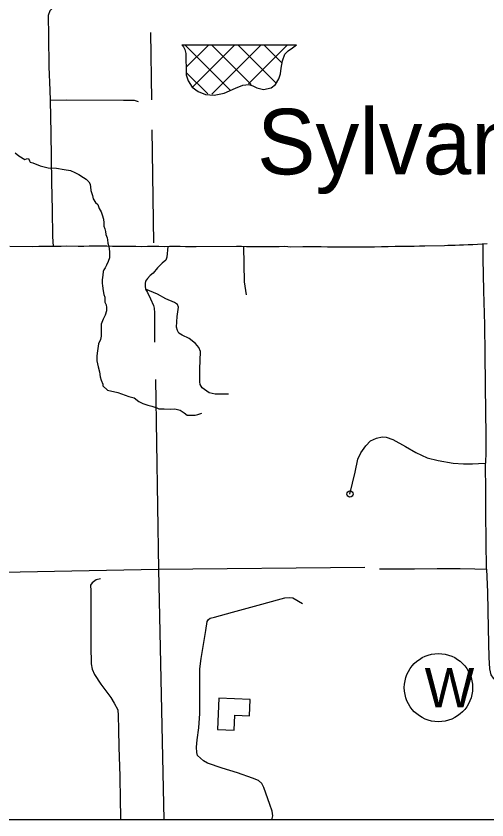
# Model space of a CAD drawing. Extents: x 1367863 to 1368197, y 380048 to 380261.
# Drawn here: x 1368028.89 to 1368043.62, y 380096.87 to 380122.01 of the extents above; entities that cross this region are included whole.
import ezdxf

# ---------------------------------------------------------------- set-up
doc = ezdxf.new("R2010")
doc.units = 0
for name, color, linetype in [('Level 24', 7, 'Continuous'), ('Level 31', 7, 'Continuous'), ('Level 32', 7, 'Continuous'), ('Level 35', 7, 'Continuous'), ('Level 45', 7, 'Continuous'), ('Level 5', 7, 'Continuous'), ('Level 57', 7, 'Continuous'), ('Level 58', 7, 'Continuous'), ('R_No Plot', 7, 'Continuous')]:
    doc.layers.add(name, color=color, linetype=linetype)

msp = doc.modelspace()

# ---------------------------------------------------------------- linework, layer by layer
at = {"layer": 'Level 31'}
for points in [[(1368043.624, 380114.886), (1368043.474, 380114.871), (1368043.325, 380114.862), (1368043.178, 380114.857), (1368043.033, 380114.852), (1368042.892, 380114.846), (1368042.758, 380114.84), (1368042.629, 380114.835), (1368042.508, 380114.833), (1368042.394, 380114.83), (1368042.29, 380114.826), (1368041.675, 380114.812), (1368041.515, 380114.814), (1368041.341, 380114.808), (1368041.153, 380114.804), (1368040.954, 380114.801), (1368040.747, 380114.798), (1368040.534, 380114.796), (1368040.32, 380114.789), (1368040.105, 380114.785), (1368039.89, 380114.786), (1368039.671, 380114.781), (1368039.458, 380114.783), (1368039.253, 380114.785), (1368039.044, 380114.783), (1368038.839, 380114.785), (1368038.636, 380114.787), (1368038.436, 380114.79), (1368038.24, 380114.79), (1368038.048, 380114.79), (1368037.86, 380114.789), (1368037.488, 380114.787)], [(1368043.496, 380114.873), (1368043.492, 380114.432), (1368043.516, 380113.421), (1368043.544, 380112.35), (1368043.552, 380111.432), (1368043.561, 380110.491), (1368043.573, 380109.602), (1368043.585, 380108.948), (1368043.585, 380108.376), (1368043.578, 380108.027)], [(1368037.488, 380114.787), (1368037.302, 380114.8), (1368037.122, 380114.797), (1368036.941, 380114.795), (1368036.769, 380114.797), (1368036.596, 380114.797), (1368036.427, 380114.796), (1368036.262, 380114.796), (1368036.103, 380114.796), (1368035.941, 380114.805), (1368035.787, 380114.801), (1368034.521, 380114.792), (1368034.357, 380114.794), (1368034.192, 380114.796), (1368034.024, 380114.8), (1368033.859, 380114.801), (1368033.692, 380114.801), (1368033.527, 380114.797), (1368033.353, 380114.8), (1368033.178, 380114.803), (1368033.002, 380114.8), (1368032.823, 380114.797), (1368032.637, 380114.802), (1368032.453, 380114.804), (1368032.272, 380114.802), (1368032.091, 380114.801), (1368031.91, 380114.804), (1368031.73, 380114.81), (1368031.552, 380114.81), (1368031.372, 380114.811), (1368031.183, 380114.814), (1368031.01, 380114.802), (1368030.832, 380114.799), (1368030.485, 380114.813), (1368030.307, 380114.808), (1368030.134, 380114.806), (1368029.961, 380114.806), (1368029.784, 380114.801), (1368029.602, 380114.799), (1368029.413, 380114.797), (1368028.693, 380114.804)], [(1368039.336, 380107.058), (1368039.494, 380107.745), (1368039.582, 380108.149), (1368039.679, 380108.352), (1368039.837, 380108.572), (1368039.978, 380108.721), (1368040.163, 380108.809), (1368040.339, 380108.853), (1368040.471, 380108.836), (1368040.682, 380108.765), (1368041.069, 380108.545), (1368041.394, 380108.361), (1368041.746, 380108.193), (1368042.098, 380108.105), (1368042.564, 380108.026), (1368042.89, 380108.009), (1368043.171, 380108), (1368043.356, 380108.017), (1368043.578, 380108.027)], [(1368043.611, 380104.714), (1368043.595, 380105.589), (1368043.584, 380106.458), (1368043.584, 380107.107), (1368043.578, 380108.027)], [(1368040.26, 380104.719), (1368041.35, 380104.719), (1368042.063, 380104.727), (1368042.78, 380104.73), (1368043.244, 380104.725), (1368043.611, 380104.714)], [(1368043.611, 380104.714), (1368043.638, 380103.995), (1368043.654, 380102.85), (1368043.681, 380101.948), (1368043.697, 380101.587), (1368043.741, 380101.408), (1368043.816, 380101.295), (1368043.897, 380101.208), (1368043.957, 380101.144), (1368044.432, 380100.843), (1368044.912, 380100.508), (1368045.112, 380100.368), (1368045.35, 380100.249), (1368045.96, 380100.033), (1368046.928, 380099.694), (1368047.36, 380099.581), (1368047.7, 380099.532), (1368048.11, 380099.494)], [(1368031.533, 380104.409), (1368031.402, 380104.372), (1368031.271, 380104.278), (1368031.22, 380104.205), (1368031.227, 380104.03), (1368031.227, 380103.251), (1368031.234, 380102.297), (1368031.242, 380101.744), (1368031.271, 380101.576), (1368031.344, 380101.416), (1368031.547, 380101.11), (1368031.853, 380100.695), (1368031.962, 380100.513), (1368032.071, 380100.309), (1368032.086, 380100.135), (1368032.093, 380099.698), (1368032.108, 380099.141), (1368032.137, 380098.239), (1368032.151, 380097.481), (1368032.159, 380096.972), (1368032.162, 380096.865)], [(1368036.892, 380096.865), (1368036.922, 380096.99), (1368036.906, 380097.144), (1368036.831, 380097.351), (1368036.64, 380097.882), (1368036.577, 380098.004), (1368036.476, 380098.1), (1368036.29, 380098.174), (1368035.818, 380098.333), (1368035.335, 380098.487), (1368034.879, 380098.636), (1368034.757, 380098.715), (1368034.571, 380098.88), (1368034.55, 380098.971), (1368034.534, 380099.136), (1368034.555, 380099.369), (1368034.614, 380099.741), (1368034.64, 380100.197), (1368034.64, 380100.903), (1368034.645, 380101.593), (1368034.683, 380101.917), (1368034.826, 380102.79), (1368034.874, 380103.072), (1368034.916, 380103.13), (1368034.964, 380103.172), (1368035.096, 380103.21), (1368035.659, 380103.364), (1368036.582, 380103.613), (1368037.065, 380103.746), (1368037.298, 380103.809), (1368037.431, 380103.825), (1368037.548, 380103.809), (1368037.85, 380103.64)]]:
    msp.add_lwpolyline(points, dxfattribs=at)
msp.add_circle((1368039.336, 380107.058), 0.097, dxfattribs=at)
at = {"layer": 'Level 32'}
for points in [[(1368032.436, 380122.274), (1368030.311, 380122.274), (1368030.018, 380122.244), (1368029.951, 380122.177), (1368029.898, 380122.027), (1368029.906, 380121.381), (1368029.921, 380120.419), (1368029.951, 380119.69), (1368029.958, 380119.375)], [(1368032.721, 380119.33), (1368032.594, 380119.375), (1368032.256, 380119.375), (1368030.476, 380119.383), (1368029.958, 380119.375), (1368029.981, 380118.353), (1368029.996, 380116.818), (1368030.018, 380115.954), (1368030.033, 380115.113), (1368030.056, 380114.806)], [(1368033.643, 380114.8), (1368033.606, 380114.474), (1368033.578, 380114.372), (1368033.457, 380114.279), (1368033.317, 380114.139), (1368033.178, 380113.971), (1368033.085, 380113.897), (1368033.001, 380113.804), (1368032.945, 380113.72), (1368032.926, 380113.646), (1368032.926, 380113.562), (1368032.945, 380113.469), (1368033.001, 380113.366), (1368033.094, 380113.162), (1368033.187, 380112.957), (1368033.215, 380112.873), (1368033.224, 380112.733), (1368033.224, 380112.398), (1368033.224, 380111.821), (1368033.224, 380111.815)], [(1368035.532, 380110.189), (1368035.122, 380110.189), (1368034.927, 380110.226), (1368034.713, 380110.384), (1368034.648, 380110.486), (1368034.638, 380110.57), (1368034.638, 380110.961), (1368034.666, 380111.52), (1368034.611, 380111.641), (1368034.508, 380111.771), (1368034.303, 380111.92), (1368034.089, 380112.032), (1368033.987, 380112.097), (1368033.941, 380112.171), (1368033.913, 380112.283), (1368033.931, 380112.609), (1368033.968, 380112.907), (1368033.941, 380112.99), (1368033.847, 380113.056), (1368033.578, 380113.167), (1368033.317, 380113.316), (1368032.945, 380113.469)]]:
    msp.add_lwpolyline(points, dxfattribs=at)
at = {"layer": 'Level 35'}
for points in [[(1368028.869, 380117.734), (1368028.981, 380117.641), (1368029.167, 380117.52), (1368029.223, 380117.548), (1368029.278, 380117.558), (1368029.316, 380117.483), (1368029.334, 380117.446), (1368029.418, 380117.418), (1368029.641, 380117.325), (1368029.809, 380117.288), (1368029.893, 380117.269), (1368030.162, 380117.25), (1368030.395, 380117.213), (1368030.6, 380117.176), (1368030.73, 380117.12), (1368030.86, 380117.055), (1368031, 380116.962), (1368031.084, 380116.906), (1368031.168, 380116.822), (1368031.214, 380116.748), (1368031.214, 380116.738), (1368031.223, 380116.673), (1368031.233, 380116.552), (1368031.279, 380116.394), (1368031.307, 380116.292), (1368031.382, 380116.18), (1368031.447, 380116.115), (1368031.493, 380115.994), (1368031.549, 380115.891), (1368031.586, 380115.798), (1368031.624, 380115.659), (1368031.633, 380115.547), (1368031.642, 380115.444), (1368031.67, 380115.351), (1368031.689, 380115.268), (1368031.698, 380115.175), (1368031.745, 380115.072), (1368031.754, 380115.016), (1368031.763, 380114.905), (1368031.791, 380114.802), (1368031.819, 380114.644), (1368031.81, 380114.448), (1368031.772, 380114.337), (1368031.726, 380114.216), (1368031.679, 380114.141), (1368031.633, 380114.076), (1368031.614, 380114.02), (1368031.605, 380113.909), (1368031.586, 380113.76), (1368031.586, 380113.657), (1368031.596, 380113.573), (1368031.614, 380113.415), (1368031.633, 380113.304), (1368031.67, 380113.22), (1368031.67, 380113.061), (1368031.707, 380112.978), (1368031.726, 380112.894), (1368031.726, 380112.792), (1368031.679, 380112.652), (1368031.614, 380112.531), (1368031.549, 380112.373), (1368031.549, 380112.131), (1368031.558, 380112), (1368031.53, 380111.889), (1368031.475, 380111.758), (1368031.437, 380111.544), (1368031.419, 380111.386), (1368031.419, 380111.228), (1368031.465, 380111.042), (1368031.503, 380110.883), (1368031.521, 380110.725), (1368031.558, 380110.623), (1368031.605, 380110.492), (1368031.605, 380110.446), (1368031.754, 380110.306), (1368032.08, 380110.241), (1368032.415, 380110.111), (1368032.582, 380110.064), (1368032.731, 380109.952), (1368032.861, 380109.887)], [(1368032.861, 380109.887), (1368033.01, 380109.841), (1368033.14, 380109.813), (1368033.299, 380109.757), (1368033.354, 380109.729), (1368033.401, 380109.729), (1368033.522, 380109.72), (1368033.736, 380109.71), (1368033.857, 380109.72), (1368034.024, 380109.682), (1368034.155, 380109.599), (1368034.248, 380109.524), (1368034.304, 380109.524), (1368034.49, 380109.524), (1368034.574, 380109.552), (1368034.704, 380109.589)]]:
    msp.add_lwpolyline(points, dxfattribs=at)
at = {"layer": 'Level 45'}
msp.add_lwpolyline([(1368036.01, 380114.801), (1368036.029, 380113.702), (1368036.085, 380113.288)], dxfattribs=at)
at = {"layer": 'Level 5'}
for points in [[(1368033.097, 380121.499), (1368033.128, 380119.391)], [(1368033.142, 380118.451), (1368033.194, 380114.914)], [(1368033.257, 380110.644), (1368033.345, 380104.694)], [(1368033.345, 380104.694), (1368012.765, 380104.306)], [(1368039.799, 380104.761), (1368033.345, 380104.694)], [(1368033.345, 380104.694), (1368033.511, 380096.865)]]:
    msp.add_lwpolyline(points, dxfattribs=at)
at = {"layer": 'Level 57'}
for p, q in [((1368034.076, 380121.109), (1368037.662, 380121.109)), ((1368035.591, 380119.698), (1368034.195, 380121.094)), ((1368034.224, 380120.42), (1368034.899, 380121.095)), ((1368034.424, 380119.797), (1368035.718, 380121.091)), ((1368036.243, 380119.869), (1368035.014, 380121.098)), ((1368035.015, 380119.565), (1368036.547, 380121.097)), ((1368037.017, 380119.919), (1368035.846, 380121.089)), ((1368036.163, 380119.89), (1368037.363, 380121.09)), ((1368037.198, 380120.561), (1368036.668, 380121.091)), ((1368034.89, 380119.576), (1368034.236, 380120.23))]:
    msp.add_line(p, q, dxfattribs=at)
msp.add_lwpolyline([(1368034.076, 380121.109), (1368034.127, 380121.053), (1368034.175, 380120.967), (1368034.207, 380120.839), (1368034.207, 380120.646), (1368034.213, 380120.394), (1368034.213, 380120.169), (1368034.277, 380119.981), (1368034.4, 380119.788), (1368034.593, 380119.649), (1368034.818, 380119.563), (1368035.091, 380119.537), (1368035.402, 380119.596), (1368035.761, 380119.756), (1368035.981, 380119.853), (1368036.168, 380119.869), (1368036.297, 380119.831), (1368036.426, 380119.767), (1368036.634, 380119.719), (1368036.876, 380119.762), (1368037.004, 380119.869), (1368037.111, 380120.046), (1368037.16, 380120.201), (1368037.186, 380120.383), (1368037.229, 380120.614), (1368037.304, 380120.823), (1368037.406, 380120.919), (1368037.535, 380121.021), (1368037.662, 380121.109)], dxfattribs=at)
msp.add_circle((1368042.103, 380101.003), 1.067, dxfattribs=at)
at = {"layer": 'Level 58'}
msp.add_lwpolyline([(1368035.234, 380100.679), (1368035.191, 380099.694), (1368035.711, 380099.671), (1368035.731, 380100.137), (1368036.196, 380100.117), (1368036.218, 380100.636)], close=True, dxfattribs=at)
at = {"layer": 'R_No Plot'}
msp.add_lwpolyline([(1367959.444, 380177.46), (1368103.344, 380177.46), (1368103.344, 380096.865), (1367959.444, 380096.865)], close=True, dxfattribs=at)

# ---------------------------------------------------------------- texts
at = {"layer": 'Level 24'}
msp.add_text('Sylvania', height=2.0492, dxfattribs=at).set_placement((1368036.43, 380117.06))
at = {"layer": 'Level 57'}
msp.add_text('W', height=1.23, dxfattribs=at).set_placement((1368041.672, 380100.388))

doc.saveas('drawing.dxf')
